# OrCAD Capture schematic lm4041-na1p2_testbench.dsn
size A; title: LM4041-N LM4041-N-Q1 Precision Micro Power Shunt Voltage Reference; rev: 1.20; note: Datasheet: SNOS641I
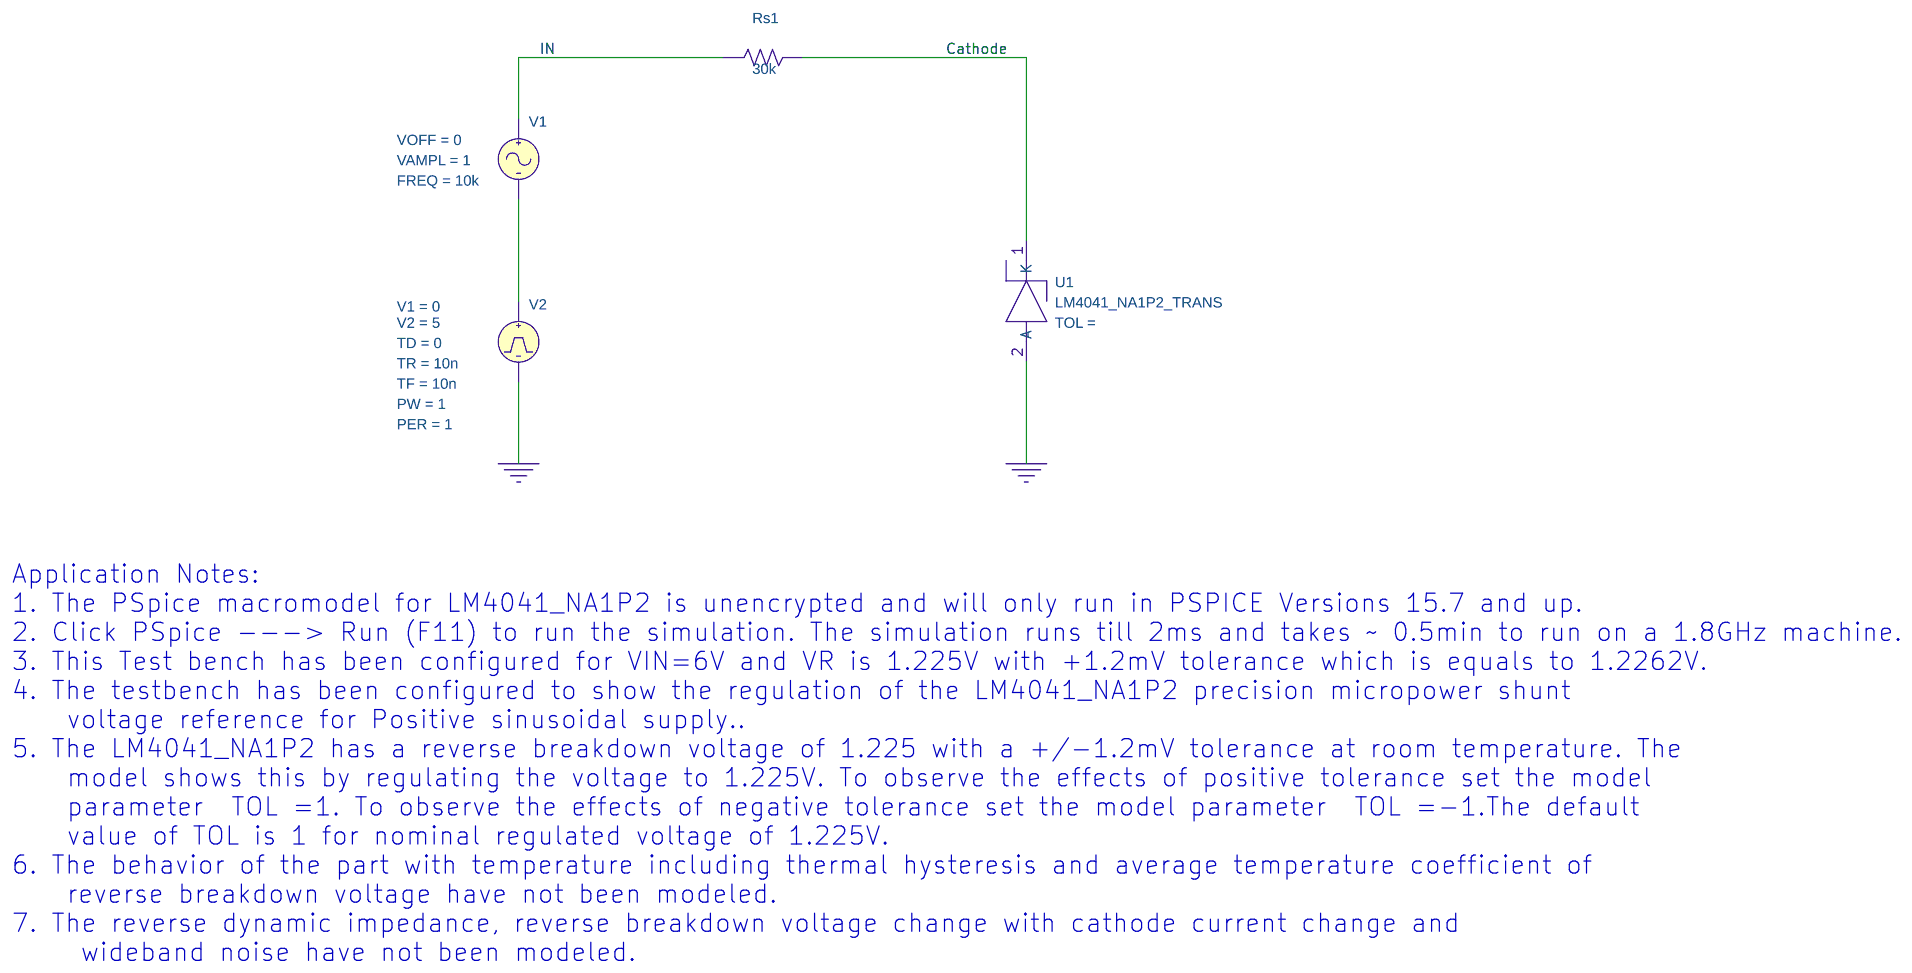
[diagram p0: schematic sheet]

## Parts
Rs1  30k  [AXRC05]
U1  LM4041_NA1P2_TRANS
V1  VSIN
V2  VPULSE

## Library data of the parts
Rs1 = R
U1 = LM4041_NA1P2
V1 = VSIN: FREQ: 10k; VAMPL: 1; VOFF: 0
V2 = VPULSE: PER: 1; PW: 1; TD: 0; TF: 10n; TR: 10n; V1: 0; V2: 5

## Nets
0: U1.2(A) V2.2(-)
Cathode: Rs1.2 U1.1(K)
IN: Rs1.1 V1.1(+)
N00271: V1.2(-) V2.1(+)

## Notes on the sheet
- Application Notes:
  1. The PSpice macromodel for LM4041_NA1P2 is unencrypted and will only run in PSPICE Versions 15.7 and up.
  2. Click PSpice ---> Run (F11) to run the simulation. The simulation runs till 2ms and takes ~ 0.5min to run on a 1.8GHz machine.
  3. This Test bench has been configured for VIN=6V and VR is 1.225V with +1.2mV tolerance which is equals to 1.2262V.
  4. The testbench has been configured to show the regulation of the LM4041_NA1P2 precision micropower shunt
      voltage reference for Positive sinusoidal supply..
  5. The LM4041_NA1P2 has a reverse breakdown voltage of 1.225 with a +/-1.2mV tolerance at room temperature. The
      model shows this by regulating the voltage to 1.225V. To observe the effects of positive tolerance set the model
      parameter  TOL =1. To observe the effects of negative tolerance set the model parameter  TOL =-1.The default
      value of TOL is 1 for nominal regulated voltage of 1.225V.
  6. The behavior of the part with temperature including thermal hysteresis and average temperature coefficient of
      reverse breakdown voltage have not been modeled.
  7. The reverse dynamic impedance, reverse breakdown voltage change with cathode current change and
       wideband noise have not been modeled.
